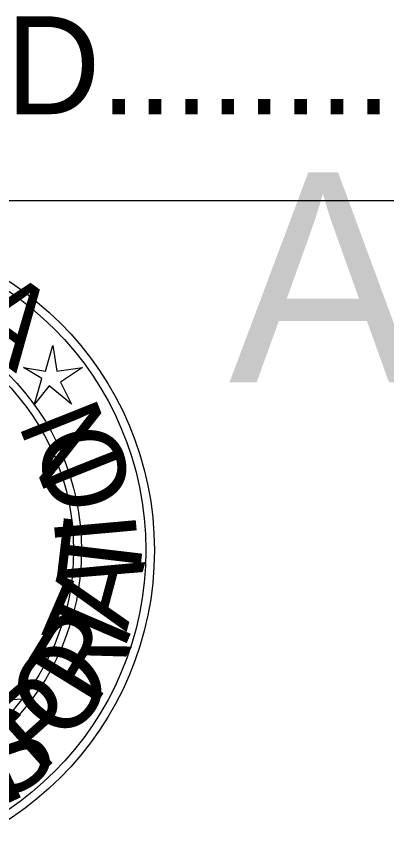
# Model space of a CAD drawing. Extents: x 0 to 1700, y 31 to 1131.
# Drawn here: x 940.8 to 967.3, y 60.8 to 118.9 of the extents above; entities that cross this region are included whole.
import ezdxf

# ---------------------------------------------------------------- set-up
doc = ezdxf.new("R2010")
doc.units = 0
for name, color, linetype in [('ANNO-TXT', 7, 'Continuous'), ('great seal', 7, 'Continuous'), ('Level 1', 7, 'Continuous'), ('SHT-BDR', 7, 'Continuous')]:
    doc.layers.add(name, color=color, linetype=linetype)

msp = doc.modelspace()

# ---------------------------------------------------------------- linework, layer by layer
at = {"layer": 'great seal'}
msp.add_lwpolyline([(943.417, 95.343), (943.68, 93.503), (945.519, 93.766), (943.943, 92.715), (944.731, 91.139), (943.154, 92.452), (942.103, 91.139), (942.629, 92.978), (941.315, 93.766), (942.892, 93.503)], close=True, dxfattribs=at)
msp.add_lwpolyline([(943.417, 95.343), (943.68, 93.503), (945.519, 93.766), (943.943, 92.715), (944.731, 91.139), (943.154, 92.452), (942.103, 91.139), (942.629, 92.978), (941.315, 93.766), (942.892, 93.503)], close=True, dxfattribs=at)
msp.add_lwpolyline([(943.417, 95.343), (943.68, 93.503), (945.519, 93.766), (943.943, 92.715), (944.731, 91.139), (943.154, 92.452), (942.103, 91.139), (942.629, 92.978), (941.315, 93.766), (942.892, 93.503)], close=True, dxfattribs=at)
msp.add_lwpolyline([(936.585, 70.906), (937.111, 70.643), (937.111, 70.643), (937.636, 70.38), (937.111, 70.117), (937.636, 69.855), (941.578, 70.117)], dxfattribs=at)
msp.add_lwpolyline([(936.585, 70.906), (937.111, 70.643), (937.111, 70.643), (937.636, 70.38), (937.111, 70.117), (937.636, 69.855), (941.578, 70.117)], dxfattribs=at)
msp.add_lwpolyline([(936.585, 70.906), (937.111, 70.643), (937.111, 70.643), (937.636, 70.38), (937.111, 70.117), (937.636, 69.855), (941.578, 70.117)], dxfattribs=at)
for radius in [22.994, 22.994, 22.994, 22.389, 22.389, 22.389, 17.779, 17.779, 17.779, 17.222, 17.222, 17.222]:
    msp.add_circle((927.669, 80.706), radius, dxfattribs=at)
at = {"layer": 'SHT-BDR'}
msp.add_lwpolyline([(62.5, 105.712), (1675, 105.712)], dxfattribs=at)

# ---------------------------------------------------------------- texts
at = {"layer": 'ANNO-TXT'}
msp.add_text('ALABAMA DEPARTMENT', height=15, rotation=360, dxfattribs=at).set_placement((955.991, 92.713))
at = {"layer": 'great seal'}
for s, height, rotation, p in [('A', 5.848, 323.98869, (936.585, 96.394)), ('A', 5.848, 323.98869, (936.585, 96.394)), ('A', 5.848, 323.98869, (936.585, 96.394)), ('N', 5.851, 111.72097, (948.41, 86.672)), ('N', 5.851, 111.72097, (948.41, 86.672)), ('N', 5.851, 111.72097, (948.41, 86.672)), ('O', 5.851, 103.43258, (949.198, 84.307)), ('O', 5.851, 103.43258, (949.198, 84.307)), ('O', 5.851, 103.43258, (949.198, 84.307)), ('I', 5.851, 95.14419, (949.461, 81.416)), ('I', 5.851, 95.14419, (949.461, 81.416)), ('I', 5.851, 95.14419, (949.461, 81.416)), ('T', 5.851, 83.25653, (949.461, 77.738)), ('T', 5.851, 83.25653, (949.461, 77.738)), ('T', 5.851, 83.25653, (949.461, 77.738)), ('A', 5.851, 74.96814, (948.672, 74.847)), ('A', 5.851, 74.96814, (948.672, 74.847)), ('A', 5.851, 74.96814, (948.672, 74.847)), ('T', 5.848, 66.67975, (947.884, 72.22)), ('R', 5.851, 58.39136, (946.308, 69.329)), ('O', 5.851, 50.10297, (944.205, 66.702)), ('O', 5.851, 50.10297, (944.205, 66.702)), ('O', 5.851, 50.10297, (944.205, 66.702)), ('P', 5.851, 41.81458, (942.366, 64.599)), ('P', 5.851, 41.81458, (942.366, 64.599)), ('P', 5.851, 41.81458, (942.366, 64.599)), ('S', 5.851, 33.52619, (939.738, 62.497)), ('S', 5.851, 33.52619, (939.738, 62.497)), ('S', 5.851, 33.52619, (939.738, 62.497)), ('N', 5.851, 25.23781, (936.585, 60.921)), ('N', 5.851, 25.23781, (936.585, 60.921)), ('N', 5.851, 25.23781, (936.585, 60.921))]:
    msp.add_text(s, height=height, rotation=rotation, dxfattribs=at).set_placement(p)
at = {"layer": 'Level 1'}
msp.add_text('VITRIFIED.................................VIT', height=7, dxfattribs=at).set_placement((901.563, 111.868))

doc.saveas('drawing.dxf')
